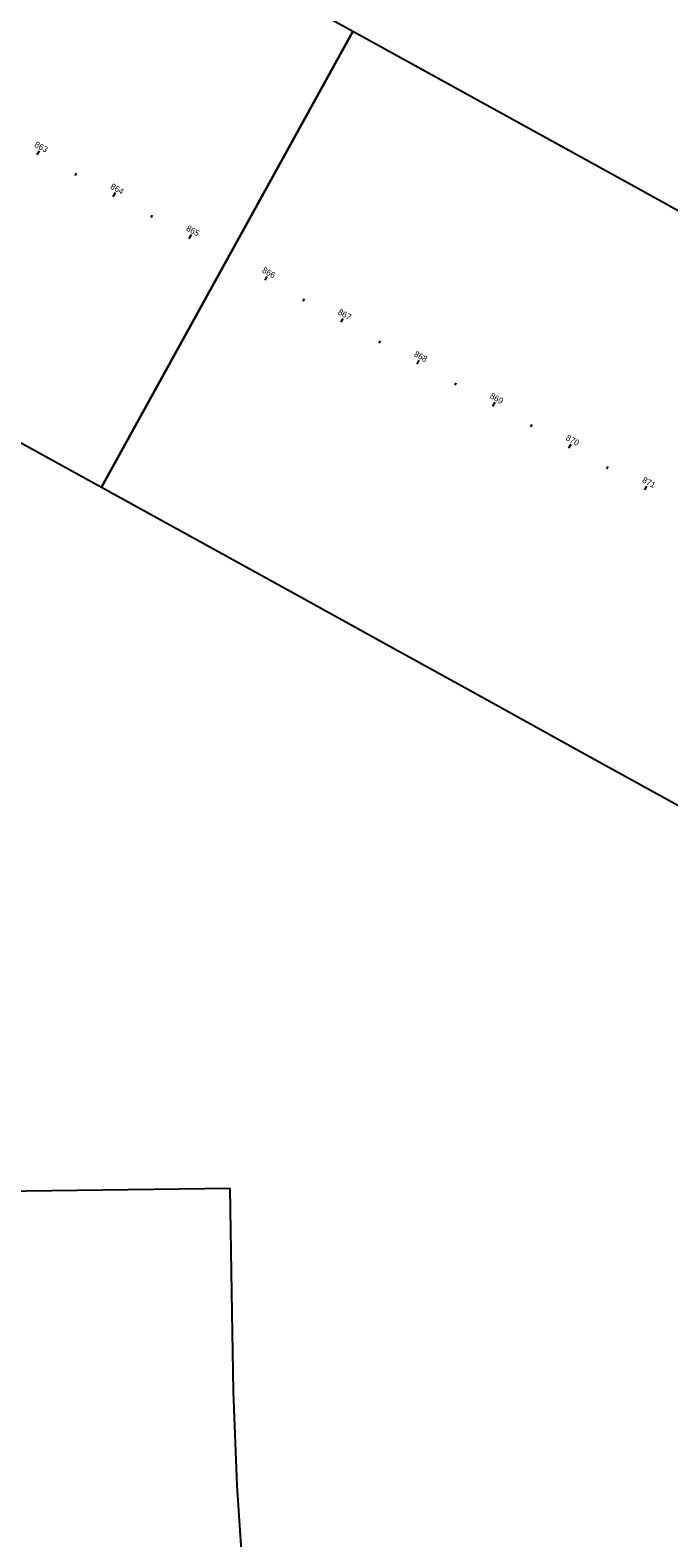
# Model space of a CAD drawing. Extents: x 75725 to 90554, y 518585 to 527848.
# Drawn here: x 87993 to 88729, y 520766 to 522504 of the extents above; entities that cross this region are included whole.
import ezdxf

# ---------------------------------------------------------------- set-up
doc = ezdxf.new("R2010")
doc.units = 0
doc.layers.add('GE_P_Alignment_100_Stations', color=7, linetype='Continuous')
doc.layers.add('SH_Named_Boundary', color=7, linetype='Continuous')

msp = doc.modelspace()

# ---------------------------------------------------------------- linework, layer by layer
at = {"layer": 'GE_P_Alignment_100_Stations'}
for p, q in [((88001.1, 522361), (88003.6, 522365.3)), ((88044.9, 522336.8), (88046.4, 522339.4)), ((88088.7, 522312.6), (88091.1, 522317)), ((88132.5, 522288.5), (88133.9, 522291.1)), ((88176.2, 522264.3), (88178.7, 522268.7)), ((88220, 522240.2), (88221.5, 522242.8)), ((88263.8, 522216), (88266.2, 522220.4)), ((88307.6, 522191.8), (88309, 522194.5)), ((88351.3, 522167.7), (88353.8, 522172)), ((88395.1, 522143.5), (88396.6, 522146.1)), ((88438.9, 522119.3), (88441.3, 522123.7)), ((88482.7, 522095.2), (88484.1, 522097.8)), ((88526.4, 522071), (88528.9, 522075.4)), ((88570.2, 522046.9), (88571.7, 522049.5)), ((88614, 522022.7), (88616.4, 522027.1)), ((88657.8, 521998.5), (88659.2, 522001.2)), ((88701.5, 521974.4), (88703.9, 521978.7))]:
    msp.add_line(p, q, dxfattribs=at)
at = {"layer": 'SH_Named_Boundary'}
for points in [[(87283.5, 523113.2), (86979.6, 522595.9), (87087.4, 522532.6), (87196.5, 522468.8), (87306.2, 522405.4), (87416.2, 522342.7), (87526.6, 522280.6), (87637.3, 522219.1), (87746.8, 522158.7), (87856.2, 522098.3), (87965.6, 522037.9), (88075.1, 521977.5), (88365, 522502.8), (88255.6, 522563.2), (88146.2, 522623.6), (88036.7, 522684), (87927.3, 522744.4), (87819.5, 522804.2), (87712, 522864.7), (87604.8, 522925.8), (87498, 522987.5), (87391.3, 523049.9)], [(88365, 522502.8), (88075.1, 521977.5), (88184.5, 521917.1), (88294, 521856.7), (88403.4, 521796.3), (88512.8, 521735.9), (88622.3, 521675.5), (88731.7, 521615), (88841.1, 521554.6), (88950.6, 521494.2), (89060, 521433.8), (89169.4, 521373.4), (89459.4, 521898.7), (89350, 521959.1), (89240.5, 522019.5), (89131.1, 522079.9), (89021.6, 522140.3), (88912.2, 522200.7), (88802.8, 522261.1), (88693.3, 522321.6), (88583.9, 522382), (88474.5, 522442.4)], [(88223.6, 521168.6), (87223.7, 521155.8), (87225.3, 521035.8), (87227.4, 520909.7), (87232.5, 520778.4), (87242.4, 520636.9), (87258.5, 520496), (87280.7, 520355.8), (87309, 520216.8), (87343.4, 520079.2), (87383.8, 519943.2), (87430, 519809.1), (88368, 520155.8), (88336, 520248.6), (88308.1, 520342.7), (88284.3, 520437.9), (88264.7, 520534), (88249.3, 520630.9), (88238.2, 520728.4), (88231.4, 520826.3), (88227.1, 520934.8), (88225.2, 521048.7)]]:
    msp.add_lwpolyline(points, close=True, dxfattribs=at)

# ---------------------------------------------------------------- texts
at = {"layer": 'GE_P_Alignment_100_Stations'}
for s, p in [('863', (87997, 522370.4)), ('864', (88084.6, 522322.1)), ('865', (88172, 522273.8)), ('866', (88259.5, 522225.5)), ('867', (88346.9, 522177.3)), ('868', (88434.6, 522128.8)), ('869', (88522.2, 522080.5)), ('870', (88609.7, 522032.2)), ('871', (88697.7, 521983.6))]:
    msp.add_text(s, height=7, rotation=331.102, dxfattribs=at).set_placement(p)

doc.saveas('drawing.dxf')
